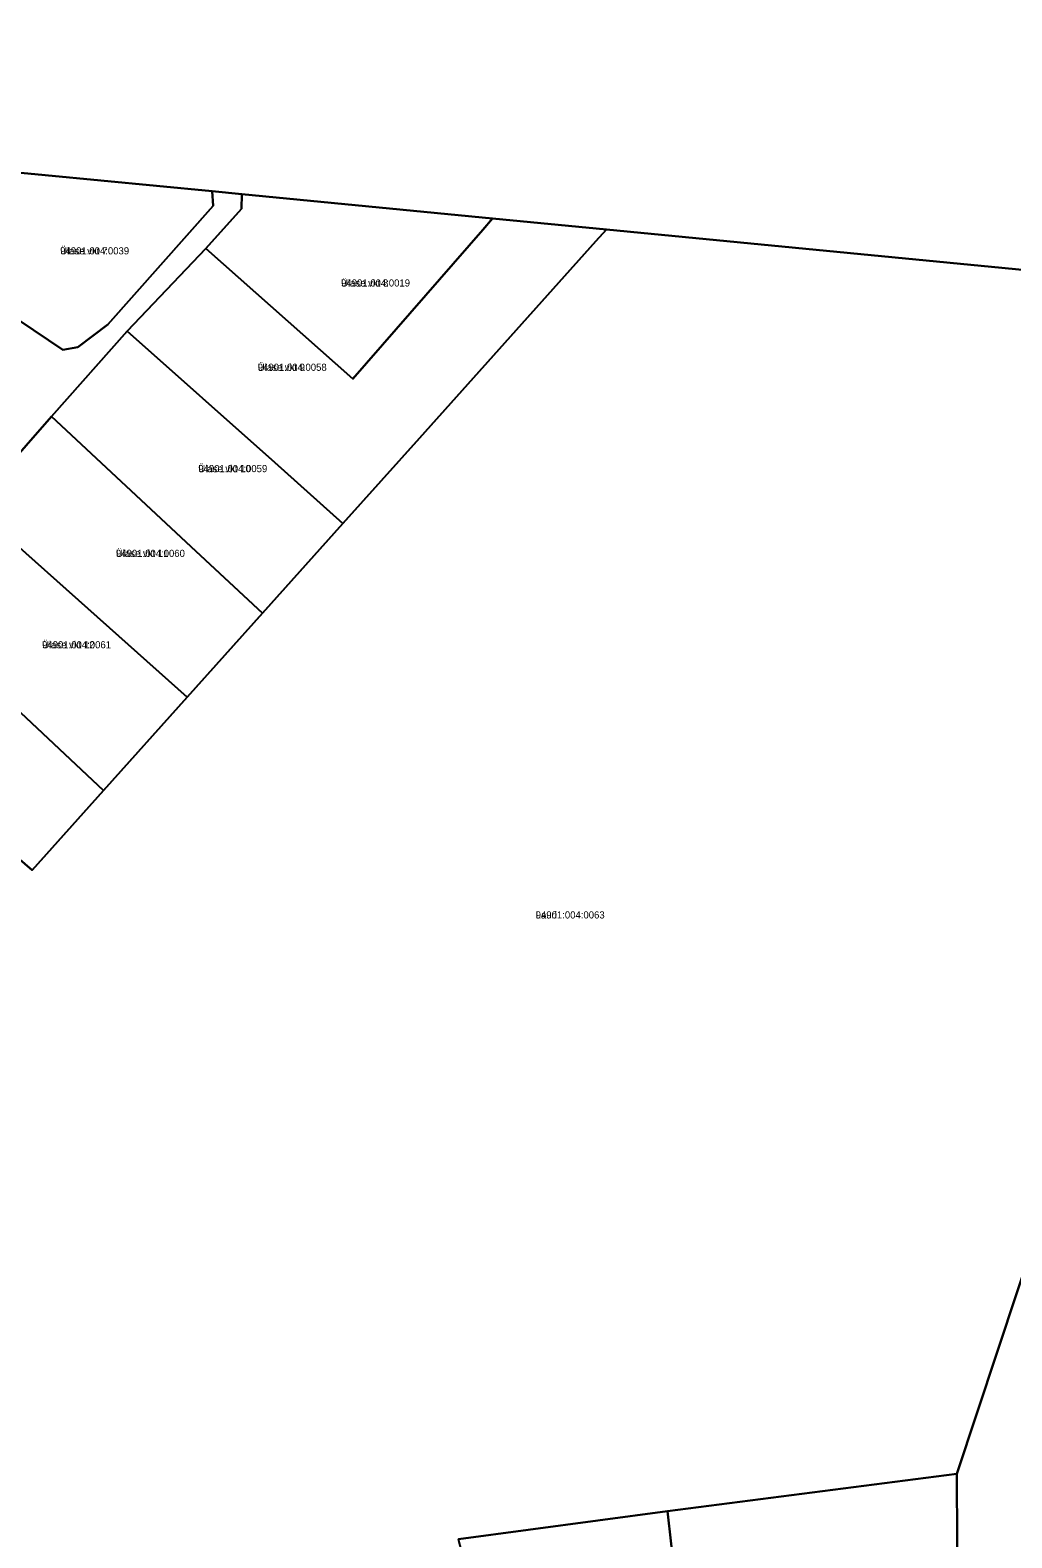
# Model space of a CAD drawing. Extents: x 647845 to 668483, y 6445298 to 6473683.
# Drawn here: x 653434 to 653640.4, y 6468125.6 to 6468442.7 of the extents above; entities that cross this region are included whole.
import ezdxf

# ---------------------------------------------------------------- set-up
doc = ezdxf.new("R2010")
doc.units = 0
for name, color, linetype in [('L_AADRESS', 7, 'Continuous'), ('PIIR', 7, 'Continuous'), ('TUNNUS', 7, 'Continuous')]:
    doc.layers.add(name, color=color, linetype=linetype)

msp = doc.modelspace()

# ---------------------------------------------------------------- linework, layer by layer
at = {"layer": 'PIIR'}
for points in [[(653710.59, 6468385.69), (653555.14, 6468400.78), (653531.19, 6468403.11), (653478.45, 6468408.19), (653472.23, 6468408.79), (653401.93, 6468415.57), (653339.11, 6468421.73), (653320.73, 6468423.39), (653317.65, 6468423.77), (653333.23, 6468613.76), (653334.45, 6468623.86), (653340.7, 6468623.38), (653833.65, 6468592.05)], [(653428.57, 6468383.73), (653440.81, 6468375.49), (653443.99, 6468376), (653450.28, 6468380.77), (653472.42, 6468405.73), (653472.23, 6468408.79), (653478.45, 6468408.19), (653478.37, 6468405.13), (653470.93, 6468396.79), (653454.36, 6468379.41), (653438.46, 6468361.42), (653421.92, 6468342.6)], [(653403.26, 6468119.5), (653392.35, 6468137.07), (653383.49, 6468153.98), (653373.63, 6468179.74), (653370.23, 6468207.36), (653369.96, 6468215.36), (653371.77, 6468214.97), (653385.51, 6468212.03), (653418.07, 6468247.81), (653403.25, 6468260.18), (653419.97, 6468278.47), (653434.4, 6468266.03), (653449.41, 6468282.78), (653466.98, 6468302.4), (653482.8, 6468320.05), (653499.74, 6468338.96), (653515.81, 6468356.89), (653552.93, 6468398.32), (653555.14, 6468400.78), (653710.59, 6468385.69)], [(653709.59, 6468382.65), (653628.86, 6468139.09), (653568.03, 6468131.26), (653524.07, 6468125.37)]]:
    msp.add_lwpolyline(points, dxfattribs=at)
for points in [[(653401.93, 6468415.57), (653472.23, 6468408.79), (653472.42, 6468405.73), (653450.28, 6468380.77), (653443.99, 6468376), (653440.81, 6468375.49), (653428.57, 6468383.73), (653402.01, 6468411.24)], [(653478.45, 6468408.19), (653531.19, 6468403.11), (653529.16, 6468400.7), (653501.8, 6468369.34), (653470.93, 6468396.79), (653478.37, 6468405.13)], [(653470.93, 6468396.79), (653501.8, 6468369.34), (653529.16, 6468400.7), (653531.19, 6468403.11), (653555.14, 6468400.78), (653552.93, 6468398.32), (653515.81, 6468356.89), (653499.74, 6468338.96), (653485.4, 6468351.74), (653454.36, 6468379.41)], [(653710.59, 6468385.69), (653722.04, 6468384.58), (653807.7, 6468367.94), (653845.89, 6468367.56), (653845.95, 6468364.95), (653854.57, 6468016.56), (653629.45, 6468033.31), (653629.23, 6468066.91), (653628.86, 6468139.09), (653709.59, 6468382.65)], [(653454.36, 6468379.41), (653485.4, 6468351.74), (653499.74, 6468338.96), (653482.8, 6468320.05), (653468.77, 6468333.14), (653438.46, 6468361.42)], [(653438.46, 6468361.42), (653468.77, 6468333.14), (653482.8, 6468320.05), (653466.98, 6468302.4), (653452.61, 6468315.22), (653421.92, 6468342.6)], [(653421.92, 6468342.6), (653452.61, 6468315.22), (653466.98, 6468302.4), (653449.41, 6468282.78), (653435.43, 6468295.87), (653413.4, 6468316.5), (653415.47, 6468318.82), (653408.1, 6468326.89)], [(653408.1, 6468326.89), (653415.47, 6468318.82), (653413.4, 6468316.5), (653435.43, 6468295.87), (653449.41, 6468282.78), (653434.4, 6468266.03), (653419.97, 6468278.47), (653388.93, 6468305.24)], [(653628.86, 6468139.09), (653629.23, 6468066.91), (653575.82, 6468061.68), (653571.1, 6468103.76), (653568.03, 6468131.26)], [(653530.48, 6468100.81), (653524.07, 6468125.37), (653568.03, 6468131.26), (653571.1, 6468103.76), (653531.05, 6468097.47)]]:
    msp.add_lwpolyline(points, close=True, dxfattribs=at)

# ---------------------------------------------------------------- texts
at = {"layer": 'L_AADRESS'}
for s, p in [('Ülase vkt 7', (653440.27, 6468395.53)), ('Ülase vkt 8', (653499.35, 6468388.77)), ('Ülase vkt 9', (653481.82, 6468371.04)), ('Ülase vkt 10', (653469.32, 6468349.73)), ('Ülase vkt 11', (653452, 6468331.91)), ('Ülase vkt 12', (653436.46, 6468312.69)), ('Lauri', (653540.28, 6468255.87))]:
    msp.add_text(s, height=1.5, dxfattribs=at).set_placement(p)
at = {"layer": 'TUNNUS'}
for s, p in [('94901:004:0039', (653440.27, 6468395.53)), ('94901:004:0019', (653499.35, 6468388.77)), ('94901:004:0058', (653481.82, 6468371.04)), ('94901:004:0059', (653469.32, 6468349.73)), ('94901:004:0060', (653452, 6468331.91)), ('94901:004:0061', (653436.46, 6468312.69)), ('94901:004:0063', (653540.28, 6468255.87))]:
    msp.add_text(s, height=1.5, dxfattribs=at).set_placement(p)

doc.saveas('drawing.dxf')
